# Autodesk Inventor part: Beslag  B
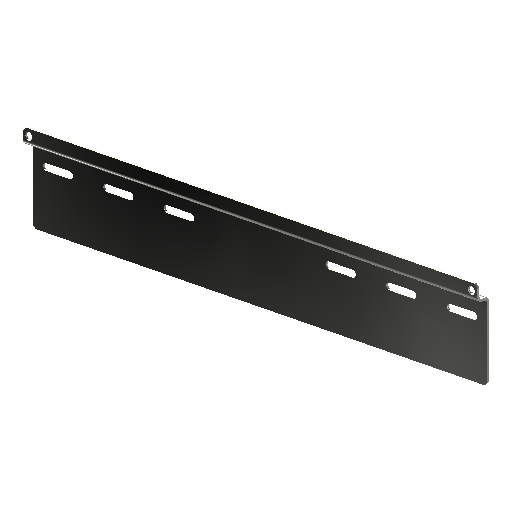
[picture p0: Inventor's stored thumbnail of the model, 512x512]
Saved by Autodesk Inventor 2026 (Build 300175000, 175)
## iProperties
Created: 2013-10
Part Number: Beslag  B
Material: Steel, Mild
Document SubType Name: Modeling
Designer: Lars Bertram Pedersen
Density: 7.85 g/cm^3
Appearance: Silver
Mass: 599.937 g
Surface Area: 794.509 cm^2
Volume: 76.4251 cm^3
Stock Number: 2002
Author: Lars Bertram Pedersen
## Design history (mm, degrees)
sketch "Sketch1"
  geometry: L1 (0, 0)-(0, 64); L2 (-2, 66)-(-6, 66); L3 (-10, 70)-(-10, 80); L4 (-8, 80)-(-8, 70); L5 (-6, 68)-(-2, 68); L6 (2, 64)-(2, 0); L7 (0, 0)-(2, 0); L8 (-8, 80)-(-10, 80); A1 r 2 centre (-6, 70) between (-8, 70) and (-6, 68); A2 r 4 centre (-6, 70) between (-10, 70) and (-6, 66); A3 r 4 centre (-2, 64) between (2, 64) and (-2, 68); A4 r 2 centre (-2, 64) between (0, 64) and (-2, 66); 1 further point
  constraints: 16 end point, 8 point on circle, 8 tangent, 4 centre point, 3 parallel, 3 perpendicular, 1 coincident, 1 equal radius, 1 vertical, 2 other
  dimensions: "d0" = 80 vertical distance of L1.start L3.end; "d1" = 2 distance between parallel lines of L6 L1; "d2" = 2 radius of A1; "d3" = 4 radius of A2; "d4" = 2 radius of A4; "d5" = 12 distance between parallel lines of L6 L3; "d6" = 14 distance between parallel lines of L8 L2
extrude "Extrusion1" new body sketch "Sketch1" stored distance "d7" = 450; taper "d8" = 0 deg
sketch "Sketch3"
  geometry: L1 (450, 10)-(0, 10) reference; L2 (450, 10)-(450, 0) reference; 2 further points
  dimensions: "d17" = 6 distance from line of L1 point (444, 4); "d46" = 6 distance from line of L2 point (444, 4)
hole "Hole2" sketch "Sketch3" diameter "d18" = 7; stored, may be unused: countersink angle "d22" = 90 deg, drill point angle "d24" = 118 deg; dims "d19" = 6, "d20" = 4, "d21" = 2, "d23" = 8
chamfer "Chamfer1" distance "d25" = 3; stored, may be unused: second distance "d26" = 2, angle "d27" = 45 deg
mirror "Mirror1"
chamfer "Chamfer2" distance "d28" = 3; stored, may be unused: second distance "d29" = 2, angle "d30" = 45 deg
sketch "Sketch4"
  geometry: L1 (0, 64)-(450, 64) reference; L2 (0, 0)-(0, 64) reference; L3 (0, 0)-(450, 0) reference; L4 (10, 50)-(40, 50); L5 (13, 47)-(37, 47); L6 (37, 53)-(13, 53); A1 r 3 centre (13, 50) between (13, 53) and (13, 47); A2 r 3 centre (37, 50) between (37, 47) and (37, 53); 2 further points
  constraints: 8 end point, 6 point on circle, 4 tangent, 2 centre point, 2 parallel, 2 point on line, 1 midpoint
  dimensions: "d31" = 30 distance of L4.start L4.end; "d32" = 6 diameter of A2; "d33" = 50 distance from line of L3 A1.centre; "d34" = 10 distance from line of L4.start L2
extrude "Extrusion2" cut sketch "Sketch4" extent not by distance; stored distance "d35" = 10; taper "d36" = 0 deg
pattern_linear "Rectangular Pattern1"
mirror "Mirror2"
chamfer "Chamfer3" distance "d40" = 3; stored, may be unused: second distance "d41" = 2, angle "d42" = 45 deg
chamfer "Chamfer4" distance "d43" = 3; stored, may be unused: second distance "d44" = 2, angle "d45" = 45 deg
body "Solid1"
